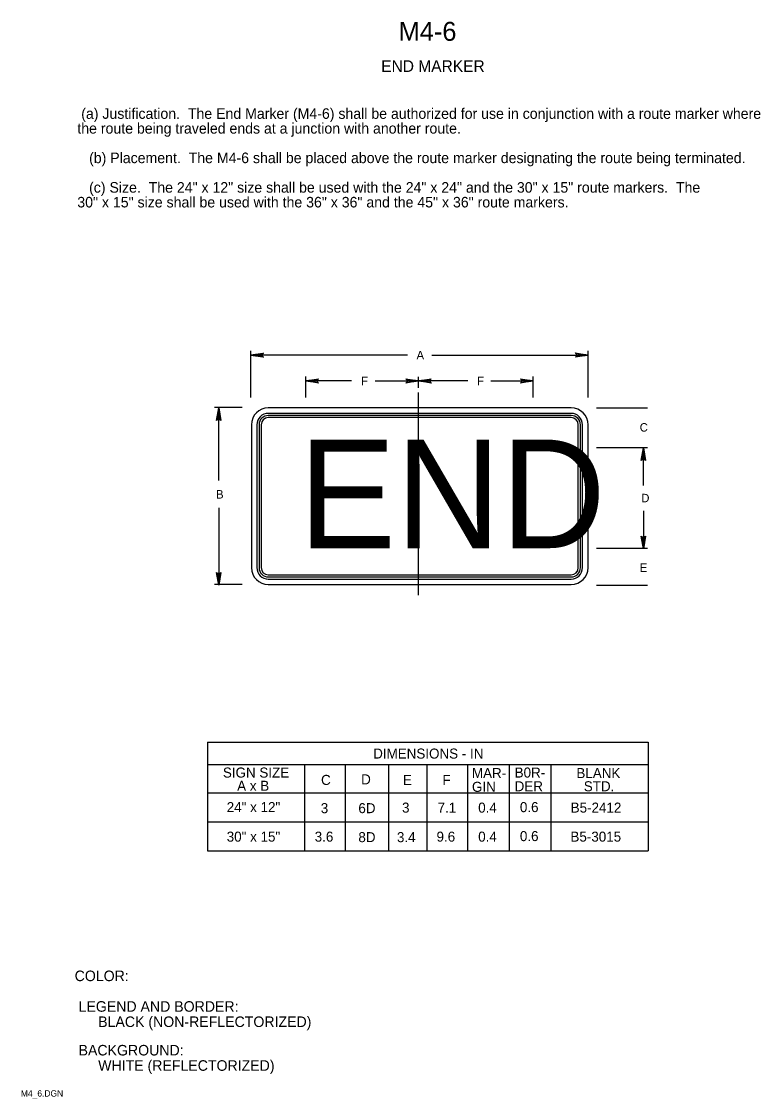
# Model space of a CAD drawing. Extents: x 0.013 to 0.188, y 0.004 to 0.259.
import ezdxf

# ---------------------------------------------------------------- set-up
doc = ezdxf.new("R2010")
doc.units = 0
for name, color, linetype in [('1', 7, 'Continuous'), ('2', 7, 'Continuous'), ('3', 7, 'Continuous')]:
    doc.layers.add(name, color=color, linetype=linetype)

# ---------------------------------------------------------------- blocks, each defined once
blk = doc.blocks.new('RARROW')
at = {"layer": '3'}
for p, q in [((-2.156, 0.285), (-2.2665, 0.384625)), ((-2.2665, 0.384625), (0, 0)), ((0, 0), (-2.2665, -0.379125)), ((-2.156, 0.285), (-2.075625, 0.12075)), ((0, 0), (-2.156, 0.285)), ((-2.14975, -0.2705), (0, 0)), ((-2.075625, 0.12075), (0, 0)), ((0, 0), (-2.074, -0.108)), ((-2.2665, -0.379125), (-2.14975, -0.2705)), ((-2.074, -0.108), (-2.14975, -0.2705))]:
    blk.add_line(p, q, dxfattribs=at)

msp = doc.modelspace()

# ---------------------------------------------------------------- linework, layer by layer
at = {"layer": '1'}
msp.add_line((0.10675, 0.12325), (0.10675, 0.17125), dxfattribs=at)
at = {"layer": '3'}
for p, q in [((0.067, 0.17012), (0.067, 0.18113)), ((0.10412, 0.18013), (0.067, 0.18013)), ((0.10988, 0.18013), (0.14688, 0.18013)), ((0.14688, 0.17012), (0.14688, 0.18113)), ((0.08, 0.17012), (0.08, 0.17509)), ((0.09087, 0.174), (0.08, 0.174)), ((0.09641, 0.174), (0.10675, 0.174)), ((0.10675, 0.17238), (0.10675, 0.175)), ((0.11837, 0.174), (0.10675, 0.174)), ((0.12387, 0.174), (0.13387, 0.174)), ((0.13387, 0.17012), (0.13387, 0.17509)), ((0.06491, 0.16775), (0.05842, 0.16775)), ((0.05942, 0.15038), (0.05942, 0.16775)), ((0.14288, 0.16762), (0.07113, 0.16762)), ((0.14288, 0.16632), (0.07113, 0.16632)), ((0.14888, 0.16762), (0.161, 0.16762)), ((0.06713, 0.16362), (0.06713, 0.12975)), ((0.06843, 0.16362), (0.06843, 0.12975)), ((0.06893, 0.16362), (0.06893, 0.12975)), ((0.06943, 0.16362), (0.06943, 0.12975)), ((0.14288, 0.16582), (0.07113, 0.16582)), ((0.14288, 0.16532), (0.07113, 0.16532)), ((0.14457, 0.12975), (0.14457, 0.16362)), ((0.14507, 0.12975), (0.14507, 0.16362)), ((0.14557, 0.12975), (0.14557, 0.16362)), ((0.14688, 0.12975), (0.14688, 0.16362)), ((0.14888, 0.15825), (0.161, 0.15825)), ((0.16, 0.15425), (0.16, 0.15825)), ((0.16, 0.14925), (0.16, 0.15825)), ((0.05942, 0.14395), (0.05942, 0.12575)), ((0.16, 0.14325), (0.16, 0.13437)), ((0.16, 0.13837), (0.16, 0.13437)), ((0.14888, 0.13437), (0.161, 0.13437)), ((0.07113, 0.12805), (0.14288, 0.12805)), ((0.06491, 0.12575), (0.05842, 0.12575)), ((0.07113, 0.12755), (0.14288, 0.12755)), ((0.07113, 0.12705), (0.14288, 0.12705)), ((0.07113, 0.12575), (0.14288, 0.12575)), ((0.14888, 0.12563), (0.161, 0.12563)), ((0.05675, 0.08837), (0.16112, 0.08837)), ((0.05675, 0.08837), (0.05675, 0.06263)), ((0.16112, 0.08837), (0.16112, 0.06263)), ((0.16112, 0.083), (0.05675, 0.083)), ((0.07967, 0.08299), (0.07967, 0.06261)), ((0.08938, 0.08299), (0.08938, 0.06261)), ((0.09959, 0.08299), (0.09959, 0.06261)), ((0.1087, 0.08299), (0.1087, 0.06261)), ((0.11834, 0.08299), (0.11834, 0.06261)), ((0.12822, 0.08299), (0.12822, 0.06261)), ((0.13809, 0.08299), (0.13809, 0.06261)), ((0.05675, 0.07637), (0.16112, 0.07637)), ((0.05675, 0.0695), (0.16112, 0.0695)), ((0.05675, 0.06263), (0.16112, 0.06263))]:
    msp.add_line(p, q, dxfattribs=at)
for centre, radius, start, end in [((0.07113, 0.16362), 0.004, 90, 180), ((0.07113, 0.16362), 0.0027, 90, 180), ((0.14288, 0.16362), 0.004, 0, 90), ((0.14288, 0.16362), 0.0027, 0, 90), ((0.07113, 0.16362), 0.0022, 90, 180), ((0.07113, 0.16362), 0.0017, 90, 180), ((0.14288, 0.16362), 0.0022, 0, 90), ((0.14288, 0.16362), 0.0017, 0, 90), ((0.07113, 0.12975), 0.004, 180, 270), ((0.07113, 0.12975), 0.0027, 180, 270), ((0.07113, 0.12975), 0.0022, 180, 270), ((0.07113, 0.12975), 0.0017, 180, 270), ((0.14288, 0.12975), 0.004, 270, 0), ((0.14288, 0.12975), 0.0027, 270, 0), ((0.14288, 0.12975), 0.0022, 270, 0), ((0.14288, 0.12975), 0.0017, 270, 0)]:
    msp.add_arc(centre, radius, start, end, dxfattribs=at)

# ---------------------------------------------------------------- block references
at = {"layer": '3', "xscale": 0.0013236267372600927, "yscale": 0.001309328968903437}
for p, rotation in [((0.067, 0.18013), 180), ((0.08, 0.174), 180), ((0.10675, 0.174), 180), ((0.05938, 0.16762), 90), ((0.16, 0.15813), 90), ((0.16, 0.13425), -90), ((0.05938, 0.12563), -90)]:
    msp.add_blockref('RARROW', p, dxfattribs=dict(at, rotation=rotation))
for p in [(0.14688, 0.18013), (0.10675, 0.174), (0.13387, 0.174)]:
    msp.add_blockref('RARROW', p, dxfattribs=at)

# ---------------------------------------------------------------- texts
at = {"layer": '1'}
for s, height, p in [('M4-6', 0.0045, (0.102, 0.25462)), ('END MARKER', 0.00275, (0.09788, 0.24725)), ('END', 0.02575, (0.07838, 0.13437)), ('COLOR:', 0.0025, (0.02525, 0.03175)), (' LEGEND AND BORDER:', 0.0024998, (0.02525, 0.0245)), ('      BLACK (NON-REFLECTORIZED)', 0.0024998, (0.02525, 0.02088)), (' BACKGROUND:', 0.0024998, (0.02525, 0.01413)), ('      WHITE (REFLECTORIZED)', 0.0024998, (0.02525, 0.0105)), ('M4_6.DGN', 0.0015, (0.0125, 0.00438))]:
    msp.add_text(s, height=height, dxfattribs=at).set_placement(p)
at = {"layer": '2'}
for s, height, p in [(' (a) Justification.  The End Marker (M4-6) shall be authorized for use in conjunction with a route marker where ', 0.00249975, (0.02588, 0.23613)), ('the route being traveled ends at a junction with another route.', 0.0024998, (0.02588, 0.23263)), ('   (b) Placement.  The M4-6 shall be placed above the route marker designating the route being terminated.', 0.00249975, (0.02588, 0.22563)), ('   (c) Size.  The 24" x 12" size shall be used with the 24" x 24" and the 30" x 15" route markers.  The  ', 0.00249975, (0.02588, 0.21863)), ('30" x 15" size shall be used with the 36" x 36" and the 45" x 36" route markers.', 0.0024998, (0.02588, 0.21513))]:
    msp.add_text(s, height=height, dxfattribs=at).set_placement(p)
at = {"layer": '3'}
for s, height, p in [('A', 0.002, (0.10625, 0.17913)), ('F', 0.002, (0.09312, 0.173)), ('F', 0.002, (0.12062, 0.173)), ('C', 0.002, (0.15913, 0.162)), ('B', 0.002, (0.05875, 0.14613)), ('D', 0.002, (0.1595, 0.14525)), ('E', 0.002, (0.15913, 0.12875)), ('DIMENSIONS - IN', 0.0023752, (0.09598, 0.0845)), ('SIGN SIZE', 0.002375, (0.06037, 0.08)), ('MAR-', 0.002375, (0.11938, 0.07988)), ('B0R-', 0.002375, (0.1295, 0.08)), ('BLANK', 0.002375, (0.14413, 0.07988)), ('A x B', 0.002375, (0.06375, 0.07687)), ('C', 0.00238, (0.08363, 0.07825)), ('D', 0.00238, (0.09312, 0.07838)), ('E', 0.00238, (0.103, 0.07825)), ('F', 0.00238, (0.11238, 0.07825)), ('STD.', 0.002375, (0.14588, 0.07675)), ('GIN', 0.002375, (0.11938, 0.07662)), ('DER', 0.002375, (0.1295, 0.07675)), ('24" x 12"', 0.002375, (0.06128, 0.07181)), ('3', 0.00238, (0.10281, 0.07169)), ('7.1', 0.002375, (0.11124, 0.07169)), ('0.4', 0.002375, (0.12086, 0.07169)), ('0.6', 0.002375, (0.13074, 0.07181)), ('B5-2412', 0.002375, (0.14277, 0.07169)), ('3', 0.00238, (0.08356, 0.07156)), ('6D', 0.002375, (0.09247, 0.07156)), ('30" x 15"', 0.002375, (0.06128, 0.06481)), ('3.6', 0.002375, (0.08212, 0.06481)), ('8D', 0.002375, (0.09247, 0.06469)), ('3.4', 0.002375, (0.10161, 0.06469)), ('9.6', 0.002375, (0.11099, 0.06481)), ('0.4', 0.002375, (0.12086, 0.06481)), ('0.6', 0.002375, (0.13074, 0.06494)), ('B5-3015', 0.002375, (0.14272, 0.06481))]:
    msp.add_text(s, height=height, dxfattribs=at).set_placement(p)

doc.saveas('drawing.dxf')
